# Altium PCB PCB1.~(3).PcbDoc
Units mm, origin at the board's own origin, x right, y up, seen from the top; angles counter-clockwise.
Board outline 100 x 50 mm, 2 copper layers (Top Layer, Bottom Layer); 61 components, 56 nets, 212 pads, 57 vias.
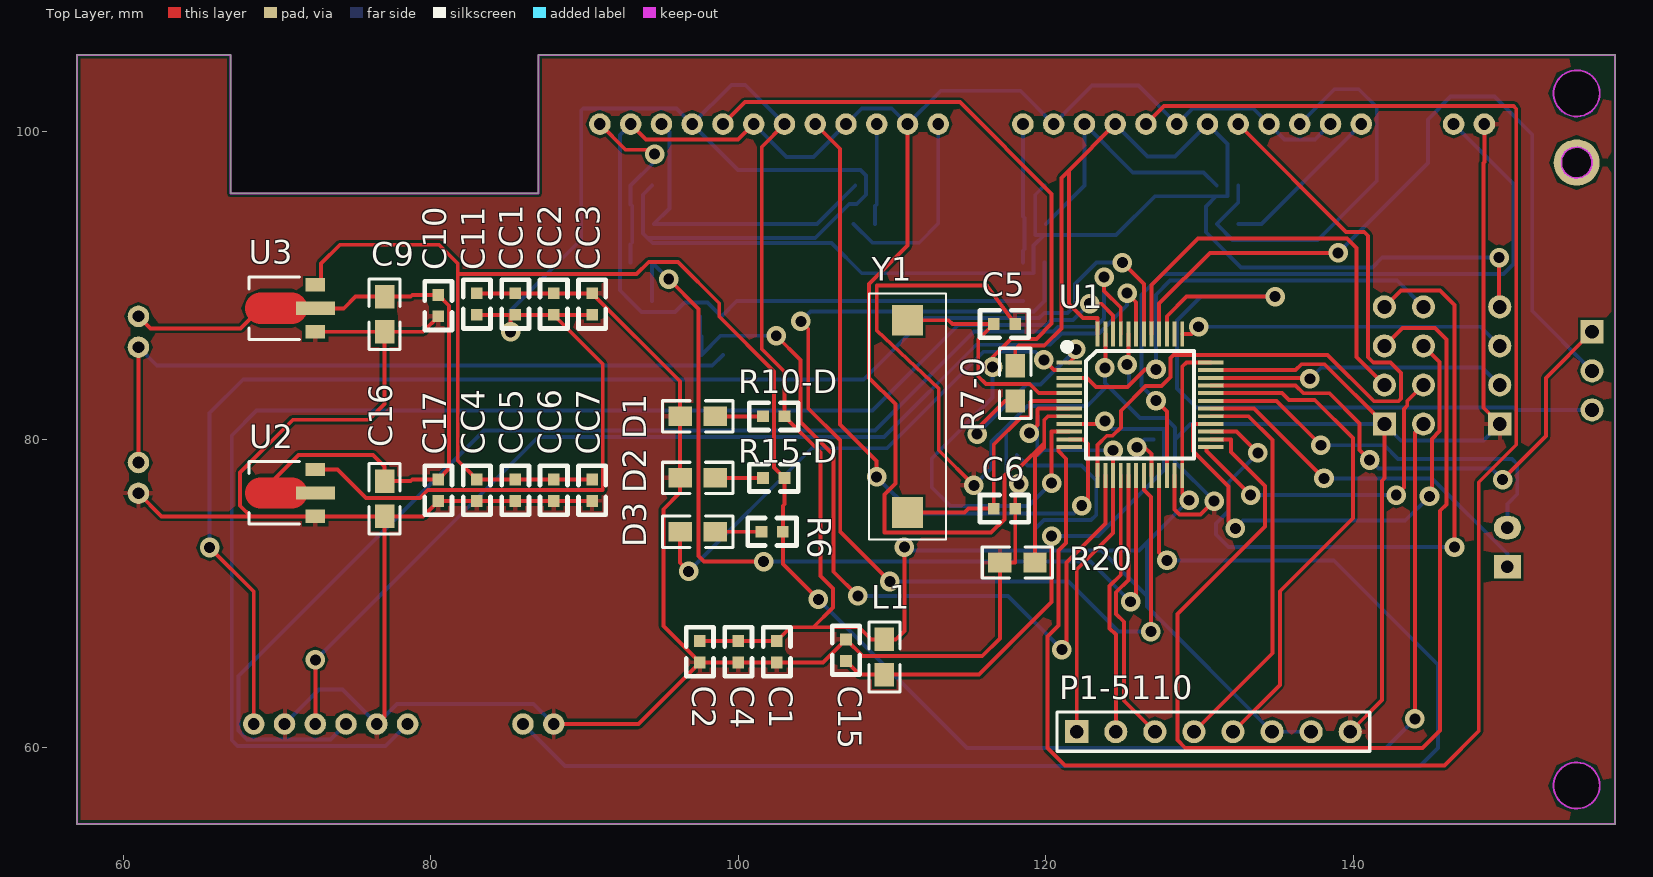
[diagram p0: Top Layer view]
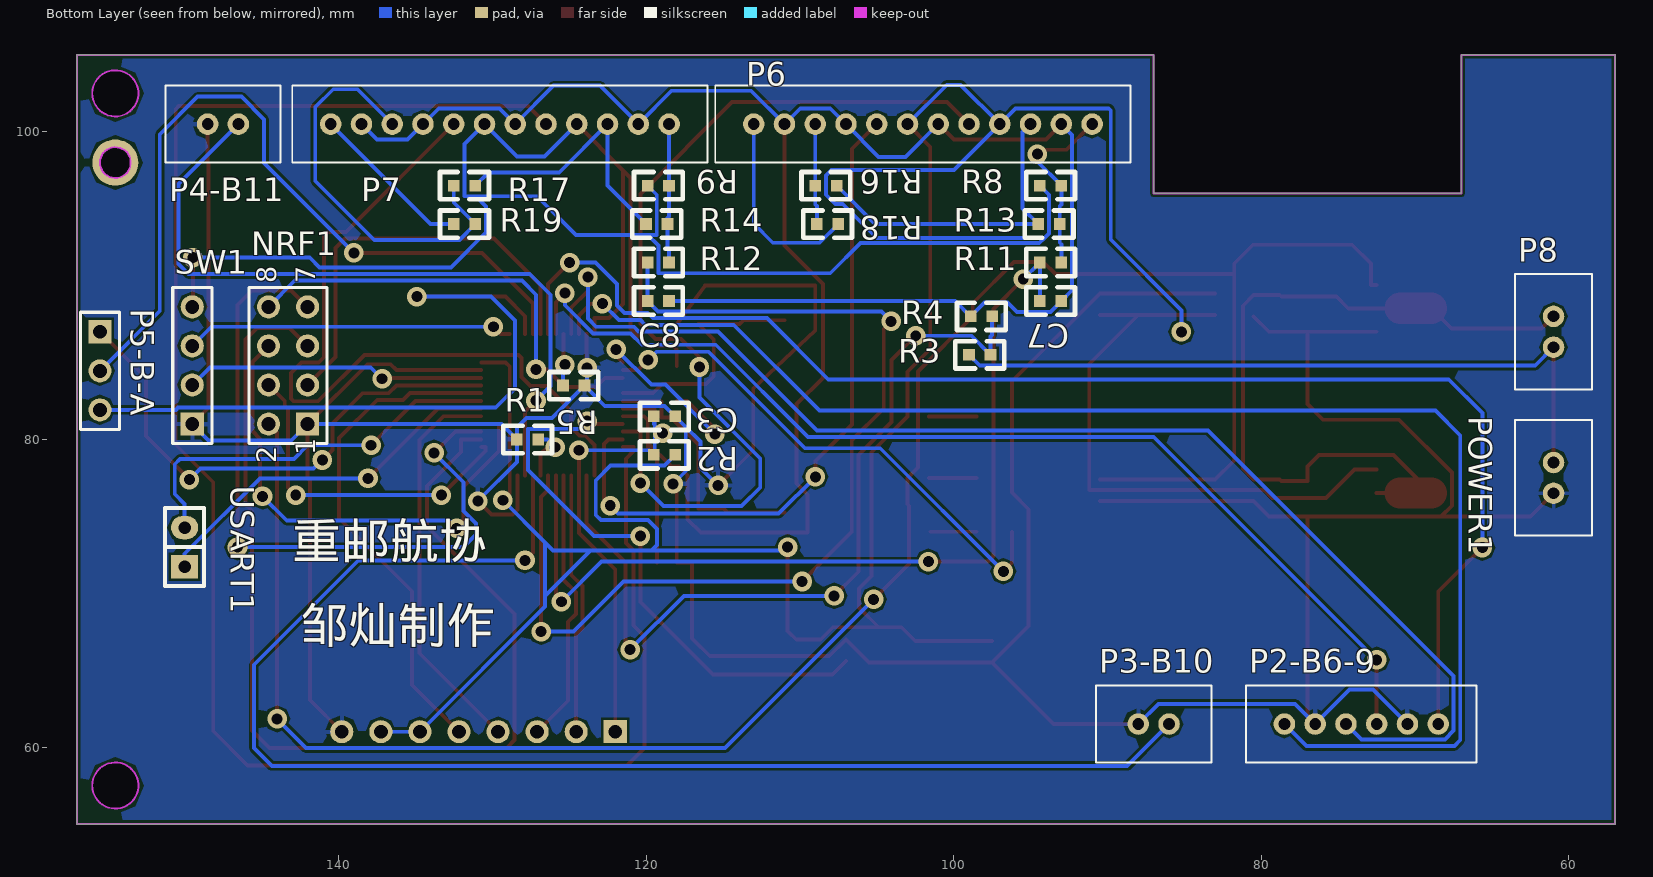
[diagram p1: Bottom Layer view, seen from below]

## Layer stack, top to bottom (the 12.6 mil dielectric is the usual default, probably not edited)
Top Solder: solder mask 0.0102, Solder Resist, Dk 3.5
Top Layer: signal copper 0.0356
Dielectric 1: dielectric 0.32, FR-4, Dk 4.8
Bottom Layer: signal copper 0.0356
Bottom Solder: solder mask 0.0102, Solder Resist, Dk 3.5

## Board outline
57,55 57,105 67,105 67,96 87,96 87,105 157,105 157,55

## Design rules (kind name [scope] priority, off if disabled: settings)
Clearance [All] p1: gap=0.178
PolygonConnect [All] p1: connectstyle=Relief reliefconductorwidth=0.254 reliefentries=4 polygonreliefangle="90 Angle" airgapwidth=0.254
RoutingVias [All] p1: holewidth=0.711 width=1.27 viastyle="Through Hole" minholewidth=0.711 minwidth=1.27 maxholewidth=0.711 maxwidth=1.27
SolderMaskExpansion [All] p1: expansion=0.102
UnpouredPolygon [All] p1: allowunpoured=FALSE
Width [All] p1: maxlimit=0.254 minlimit=0.254 preferedwidth=0.254
29 further rules are at their usual default settings.

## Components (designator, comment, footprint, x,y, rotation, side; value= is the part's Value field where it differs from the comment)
C1 "cap" 0603c 102.5,65.5 r90 top
C2 "cap" 0603c 97.5,65.5 r90 top
C3 "cap" 0603c 118.103,81.5 r0 bottom
C4 "cap" 0603c 100,65.5 r90 top
C5 "cap" 0603c 118,87.5 r180 top
C6 "cap" 0603c 118,75.5 r180 top
C7 "cap" 0603c 93,89 r0 bottom
C8 "cap" 0603c 118.5,89 r0 bottom
C9 "cap" 0805 77,87 r90 top
C10 "cap" 0603c 80.5,88 r90 top
C11 "cap" 0603c 83,89.5 r270 top
C15 "cap" 0603c 107,67 r270 top
C16 "cap" 0805 77,75 r90 top
C17 "cap" 0603c 80.5,76 r90 top
CC1 "cap" 0603c 85.5,89.5 r270 top
CC2 "cap" 0603c 88,89.5 r270 top
CC3 "cap" 0603c 90.5,89.5 r270 top
CC4 "cap" 0603c 83,76 r90 top
CC5 "cap" 0603c 85.5,76 r90 top
CC6 "cap" 0603c 88,76 r90 top
CC7 "cap" 0603c 90.5,76 r90 top
D1 "LED0" 0805 98.5,81.5 r180 top
D2 "LED0" 0805 98.5,77.5 r180 top
D3 "LED0" 0805 98.5,74 r180 top
L1 "Inductor" 0805 109.5,67 r270 top
NRF1 "Header 4X2" HDR2X4 142,81 r90 bottom
P1-5110 "Header 8" HDR1X8 122,61 r0 top
P2-B6-9 "Header 6" 6p 73.5,61.5 r0 bottom
P3-B10 "Header 2" 2p 87,61.5 r0 bottom
P4-B11 "Header 2" 2p 147.5,100.5 r0 bottom
P5-B-A "Header 3" HDR1X3 155.5,87 r270 bottom
P6 "Header 12" 12p 102,100.5 r0 bottom
P7 "Header 12" 12p 129.5,100.5 r0 bottom
P8 "Header 2" 2p 61,87 r90 bottom
POWER1 "CON2" 2p 61,77.5 r90 bottom
R1 "res" 0603c 127,80 r0 bottom
R2 "10K" 0603c 119.5,79 r180 bottom
R3 "10K" 0603c 97.603,85.5 r0 bottom
R4 "10K" 0603c 98.897,88 r180 bottom
R5 "res" 0603c 124,83.5 r0 bottom
R6 "1K" 0603c 101.5,74 r0 top
R7-0 "0R" 0805 118,82.5 r90 top
R8 "10K" 0603c 93,96.5 r0 bottom
R9 "10K" 0603c 118.5,96.5 r0 bottom
R10-D "res" 0603c 103,81.5 r180 top
R11 "1K" 0603c 93,91.5 r0 bottom
R12 "1K" 0603c 118.5,91.5 r0 bottom
R13 "10K" 0603c 94.5,94 r180 bottom
R14 "10K" 0603c 120,94 r180 bottom
R15-D "res" 0603c 103,77.5 r180 top
R16 "10K" 0603c 109,96.5 r180 bottom
R17 "10K" 0603c 132.5,96.5 r180 bottom
R18 "10K" 0603c 107.5,94 r0 bottom
R19 "10K" 0603c 132.5,94 r180 bottom
R20 "0R" 0805 117,72 r0 top
SW1 "Header 4" HDR1X4 149.5,81 r90 bottom
U1 "STM32F103C8T6" LQFP48S 121.5,85 r0 top
U2 "XC6203E" SOT-89 72.5,75 r90 top
U3 "XC6203E" SOT-89 72.5,87 r90 top
USART1 "CON2" SIP2 150,73 r90 bottom
Y1 "5032xtal" 晶振 111,81.5 r90 top

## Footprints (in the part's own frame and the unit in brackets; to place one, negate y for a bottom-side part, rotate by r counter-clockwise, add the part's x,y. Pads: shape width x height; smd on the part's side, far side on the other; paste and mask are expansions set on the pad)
2p [mil]
  round 55 hole 30: 1(-39.37,0) 2(39.37,0)
  silkscreen extent -148,-98 148,98
6p [mil]
  round 55 hole 30: 1(-196.85,0) 2(-118.11,0) 3(-39.37,0) 4(39.37,0) 5(118.11,0) 6(196.85,0)
  silkscreen extent -295,-98 295,98
12p [mil]
  round 55 hole 30: 1(-433.07,0) 2(-354.33,0) 3(-275.59,0) 4(-196.85,0) 5(-118.11,0) 6(-39.37,0) 7(39.37,0) 8(118.11,0) 9(196.85,0) 10(275.59,0) 11(354.33,0) 12(433.07,0)
  silkscreen extent -531,-98 531,98
0603c [mil]
  rect 30x30 smd: 1(0,0) 2(55,0)
  silkscreen extent -35,-35 90,35
0805 [mil]
  rect 60x50 smd: 1(0,0) 2(90,0)
  silkscreen extent -45,-40 135,40
HDR1X3 [mm] "Connector; Header; 3 Position"
  rect 1.5x1.5 hole 0.9: 1(0,0)
  round 1.5 hole 0.9: 2(2.54,0) 3(5.08,0)
  silkscreen extent -1.27,-1.27 6.35,1.27
HDR1X4 [mm] "Connector; Header; 4 Position"
  rect 1.5x1.5 hole 0.9: 1(0,0)
  round 1.5 hole 0.9: 2(2.54,0) 3(5.08,0) 4(7.62,0)
  silkscreen extent -1.27,-1.27 8.89,1.27
HDR1X8 [mm] "Connector; Header; 8 Position"
  rect 1.5x1.5 hole 0.9: 1(0,0)
  round 1.5 hole 0.9: 2(2.54,0) 3(5.08,0) 4(7.62,0) 5(10.16,0) 6(12.7,0) 7(15.24,0) 8(17.78,0)
  silkscreen extent -1.27,-1.27 19.05,1.27
HDR2X4 [mm] "Connector; Header; 4x2 Position"
  rect 1.5x1.5 hole 0.9: 1(0,0)
  round 1.5 hole 0.9: 2(0,2.54) 3(2.54,0) 4(2.54,2.54) 5(5.08,0) 6(5.08,2.54) 7(7.62,0) 8(7.62,2.54)
  silkscreen extent -1.27,-1.27 8.89,3.81
LQFP48S [mil] "DPIN-0.5"
  rect 65x10 smd: 1(0.43,0.29) 2(0.43,-19.39) 3(0.43,-39.08) 4(0.43,-58.76) 5(0.43,-78.45) 6(0.43,-98.13) 7(0.43,-117.82) 8(0.43,-137.5) 9(0.43,-157.19) 10(0.43,-176.87) 11(0.43,-196.56) 12(0.43,-216.24) 25(362.63,-216.24) 26(362.63,-196.56) 27(362.63,-176.87) 28(362.63,-157.19) 29(362.63,-137.5) 30(362.63,-117.82) 31(362.63,-98.13) 32(362.63,-78.45) 33(362.63,-58.76) 34(362.63,-39.08) 35(362.63,-19.39) 36(362.63,0.29)
  rect 10x65 smd: 13(73.26,-289.08) 14(92.95,-289.08) 15(112.63,-289.08) 16(132.32,-289.08) 17(152,-289.08) 18(171.69,-289.08) 19(191.37,-289.08) 20(211.06,-289.08) 21(230.74,-289.08) 22(250.43,-289.08) 23(270.11,-289.08) 24(289.8,-289.08) 37(289.8,73.13) 38(270.11,73.13) 39(250.43,73.13) 40(230.74,73.13) 41(211.06,73.13) 42(191.37,73.13) 43(171.69,73.13) 44(152,73.13) 45(132.32,73.13) 46(112.63,73.13) 47(92.95,73.13) 48(73.26,73.13)
  silkscreen extent -10,-246 319,46
SIP2 [mil]
  rect 60x70 hole 32: 1(-50,0)
  oval 60x70 hole 32: 2(50,0)
  silkscreen extent -100,-50 100,50
SOT-89 [mil]
  rect 34x50 smd: 1(0,0) 3(120,0)
  rect 34x100 smd: 2(60,0)
  Top Layer lines w80: 60,140 60,60
  silkscreen extent -20,40 140,170
晶振 [mm]
  rect 2x2 smd: 1(-6.25,0) 2(6.25,0)
  silkscreen extent -8,-2.5 8,2.5

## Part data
D1 D2 D3: "Typical INFRARED GaAs LED"
NRF1: "Header, 4-Pin, Dual row"
P1-5110: "Header, 8-Pin"
P2-B6-9: "Header, 6-Pin"
P3-B10 P4-B11 P8: "Header, 2-Pin"
P5-B-A: "Header, 3-Pin"
P6 P7: "Header, 12-Pin"
R2 R3 R4 R6 R7-0 R8 R9 R11 R12 R13 R14 R16 R17 R18 R19 R20: library part RES
SW1: "Header, 4-Pin"
U2 U3: library part XC6203

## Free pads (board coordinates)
  round 3 hole 3: 0(154.5,102.5) 1(154.5,57.5)
  round 3 hole 2: 2(154.5,98)

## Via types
v1: diameter 1.27, hole 0.711, Top Layer to Bottom Layer, 57 vias

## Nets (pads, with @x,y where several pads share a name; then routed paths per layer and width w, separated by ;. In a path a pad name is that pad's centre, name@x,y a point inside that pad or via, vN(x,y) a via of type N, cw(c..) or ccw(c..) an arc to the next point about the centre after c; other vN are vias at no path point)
3.3_2: CC4.2 CC5.2 CC6.2 CC7.2 NRF1.2 R6.2 R15-D.1 U3.3 | length 137.1
  Top Layer w0.254: U3.3 72.873,90.048 72.873,91.44 74.092,92.659 80.543,92.659 81.763,91.44 81.763,90.754 ; CC7.2 CC6.2 CC5.2 CC4.2 81.763,78.634 81.763,90.754 ; v1(105.207,69.596) 102.897,71.906 R6.2 102.897,75.692 103,75.795 R15-D.1 102.311,78.189 102.311,84.43 98.761,87.979 98.761,88.854 96.066,91.549 94.176,91.549 93.382,90.754 81.763,90.754 ; v1(143.986,61.828) 143.986,80.446 NRF1.2
  Bottom Layer w0.254: v1(105.207,69.596) 114.859,59.944 142.102,59.944 v1(143.986,61.828)
3.3V: C1.2 C2.2 C4.2 C11.2 CC1.2 CC2.2 CC3.2 L1.1 P1-5110.6 P1-5110.7 P6.4 P6.7 P7.4 P7.7 R2.2 R7-0.2 R8.2 R9.2 R10-D.1 SW1.4 U1.24 U1.36 U1.48 U2.3 | length 349
  Top Layer w0.254: U2.3 73.946,78.048 75.794,76.2 79.299,76.2 79.807,76.708 91.186,76.708 91.186,84.917 CC2.2 ; C11.2 CC1.2@85.192,88.103 ; v1(85.192,86.995) CC1.2@85.192,88.103 ; CC3.2 CC2.2 ; C2.2 C4.2 C1.2 103.396,67.793 104.869,67.793 ; P6.7 101.524,99.024 101.524,85.877 103,84.401 R10-D.1 105.331,79.169 105.331,71.12 106.147,70.305 106.147,69.07 104.869,67.793 ; v1(110.795,73) 110.795,67.559 110.236,67 L1.1 108.641,67 107.848,67.793 104.869,67.793 ; R7-0.2 118,85.852 118.254,86.106 119.888,86.106 121.006,87.224 121.006,97.006 121.488,97.488 ; U1.48 123.361,87.884 122.403,87.884 121.488,88.798 121.488,97.488 ; P7.4 121.488,97.488 ; v1(129.311,76.048) 128.861,76.498 U1.24 128.861,84.735 129.134,85.007 U1.36 ; v1(149.454,91.821) 149.454,88.666 SW1.4 ; CC1.2@85.192,88.103 CC1.2 CC2.2
  Bottom Layer w0.254: v1(85.192,86.995) 85.192,88.392 89.789,92.989 89.789,101.397 89.916,101.524 95.976,101.524 P6.4 ; R8.2 93.802,95.905 93.802,93.396 94.107,93.091 ; P6.7 100.452,103.048 99.548,103.048 P6.4 ; v1(110.795,73) 111.024,72.77 123.622,72.77 126.568,69.825 ; R2.2 118.795,78.308 122.301,78.308 123.266,77.343 123.266,75.082 122.936,74.752 119.863,74.752 119.278,74.168 119.278,73.127 119.634,72.771 126.035,72.771 126.568,73.304 ; R9.2 119.304,95.907 119.304,93.294 119.888,93.294 ; P7.4 126.6,98.4 128.4,98.4 P7.7 131.801,99.199 131.801,95.809 131.064,95.809 ; v1(129.311,76.048) 126.568,73.304 ; P1-5110.7 P1-5110.6 126.568,69.132 126.568,69.825 ; v1(149.454,91.821) 141.862,91.821 141.226,91.185 132.69,91.185 130.404,93.472 130.404,95.148 131.064,95.809 ; 94.107,93.091 94.437,92.761 106.07,92.761 108.026,90.805 119.202,90.805 119.202,92.608 119.888,93.294 ; 94.107,93.091 105.004,93.091 107.213,95.301 107.696,95.301 108.306,95.91 108.306,97.155 107.95,97.511 99.989,97.511 P6.4 ; 119.888,93.294 124.562,93.294 127.076,95.809 131.064,95.809 ; 126.568,69.825 126.568,73.304
ADC_KEY_L: C7.2 R11.2 U1.18 | length 60.5
  Top Layer w0.254: v1(95.479,90.418) 97.409,88.488 97.409,72.415 97.765,72.06 v1(101.651,72.06) ; v1(125.501,69.447) 125.861,69.807 U1.18
  Bottom Layer w0.254: C7.2 R11.2 v1(95.479,90.418) ; v1(101.651,72.06) 122.889,72.06 v1(125.501,69.447)
ADC_KEY_R: C8.2 R12.2 U1.19 | length 66.8
  Top Layer w0.254: v1(104.064,87.681) 104.546,87.198 104.546,82.017 106.629,79.934 106.629,73.99 v1(109.855,70.764) ; U1.19 126.361,76.708 126.822,76.247 v1(126.822,67.513)
  Bottom Layer w0.254: v1(104.064,87.681) 104.697,88.314 119.211,88.314 C8.2 R12.2 ; v1(109.855,70.764) 121.467,70.764 124.719,67.513 v1(126.822,67.513)
ADC_PITCH: P7.5 U1.12 | length 116.5
  Top Layer w0.254: U1.12 120.802,79.507 120.802,79.254 121.31,78.746 121.31,73.279 120.802,72.771 120.802,67.894 120.091,67.183 120.091,59.944 121.234,58.801 145.898,58.801 148.133,61.036 148.133,77.216 150.571,79.654 150.571,101.498 150.393,101.676 127.676,101.676 P7.5
ADC_POWER: R3.1 R4.2 U1.14 | length 54.2
  Top Layer w0.254: v1(102.464,86.741) 104.053,85.152 104.053,81.124 106.197,78.979 106.197,71.399 v1(107.772,69.825) ; v1(121.031,66.332) 121.323,66.624 121.323,72.011 123.861,74.549 U1.14
  Bottom Layer w0.254: R4.2 97.5,86.793 97.603,86.69 R3.1 98.844,86.741 v1(102.464,86.741) ; v1(107.772,69.825) 117.538,69.825 v1(121.031,66.332)
ADC_ROLL: P7.8 U1.13 | length 50.4
  Top Layer w0.254: U1.13 123.361,79.647 123.952,80.239 124.333,80.239 124.866,80.772 124.866,81.864 126.467,83.464 127.508,83.464 128.092,84.049 128.092,85.293 128.295,85.496 138.303,85.496 141.314,82.485 142.912,82.485 143.078,82.652 143.078,84.328 142.392,85.014 141.275,85.014 140.945,85.344 140.945,93.242 140.689,93.497 139.503,93.497 P7.8
ADC_THR: P6.5 U1.10 | length 61.1
  Top Layer w0.254: P6.5 100.43,101.93 114.402,101.93 120.371,95.961 120.371,87.525 119.383,86.538 117.729,86.538 116.535,85.344 v1(116.535,84.709) ; v1(120.371,77.165) 120.371,80.507 U1.10
  Bottom Layer w0.254: v1(116.535,84.709) 116.535,82.728 112.573,78.765 112.573,76.886 113.792,75.667 118.872,75.667 v1(120.371,77.165)
ADC_YAW: P6.8 U1.11 | length 44.6
  Top Layer w0.254: P6.8 106.603,98.897 106.603,80.976 108.991,78.588 v1(108.991,77.572) ; U1.11 122.428,80.007 122.733,79.703 122.733,76.1 v1(122.324,75.692)
  Bottom Layer w0.254: v1(108.991,77.572) 111.379,75.184 121.816,75.184 v1(122.324,75.692)
AGND: C7.1 C8.1 P6.2 P6.6 P6.9 P6.11 P7.2 P7.6 P7.9 P7.11 R4.1 R20.2 U1.8 | length 147.7
  Top Layer w0.254: P6.2 94.008,99.492 99.992,99.492 P6.6 ; P6.11 111,92.611 108.5,90.111 108.5,84.007 110.211,82.296 110.211,77.127 109.512,76.429 109.512,73.939 116.434,73.939 117.297,74.803 117.297,77.669 117.856,78.228 118.335,78.228 119.888,79.781 ; R20.2 119.286,78.875 119.888,79.477 119.888,79.781 ; U1.8 120.142,81.507 119.888,81.253 119.888,79.781
  Bottom Layer w0.254: P6.2 92.304,99.804 92.304,89.696 C7.1 93.71,88.29 95.885,88.29 96.495,88.9 97.997,88.9 R4.1 99.897,89 C8.1 ; P6.6 103.126,98.374 104.874,98.374 P6.9 108.024,101.524 109.976,101.524 P6.11 113.167,102.667 118.333,102.667 P7.2 122.997,102.997 126.003,102.997 P7.6 129.524,101.524 133.476,101.524 P7.9 135.508,99.492 137.492,99.492 P7.11
AVDD: C15.2 L1.2 U1.9 | length 38.2
  Top Layer w0.254: C15.2 107.889,64.714 L1.2 115.641,64.714 120.371,69.444 v1(120.371,73.711) ; U1.9 123.639,81.007 v1(123.825,81.194)
  Bottom Layer w0.254: v1(120.371,73.711) 123.393,73.711 127.686,78.003 127.686,80.686 124.333,80.686 v1(123.825,81.194)
BAT: P8.1 POWER1.2 R3.2 | length 46.3
  Top Layer w0.254: POWER1.2 P8.1
  Bottom Layer w0.254: P8.1 62.194,84.806 98.306,84.806 R3.2
BOOT0: R5.2 U1.44 | length 3.4
  Top Layer w0.254: v1(125.273,84.861) 125.361,84.949 U1.44
  Bottom Layer w0.254: v1(125.273,84.861) 125.397,84.737 R5.2
BOOT1: R1.1 U1.20 | length 3.8
  Top Layer w0.254: v1(125.908,79.492) 126.416,79.492 126.861,79.047 U1.20
  Bottom Layer w0.254: v1(125.908,79.492) 126.416,80 R1.1
CE: P1-5110.2 U1.16 | length 17.1
  Top Layer w0.254: P1-5110.2 124.54,67.306 124.13,67.716 124.13,70.46 124.861,71.191 U1.16
CLK: P1-5110.5 U1.32 | length 32.8
  Top Layer w0.254: U1.32 135.352,83.007 135.791,82.569 137.471,82.569 139.954,80.086 139.954,74.879 135.204,70.129 135.204,64.044 P1-5110.5
DC: P1-5110.3 U1.17 | length 18
  Top Layer w0.254: U1.17 125.361,70.864 124.562,70.065 124.562,68.656 125.07,68.148 125.07,63.01 P1-5110.3
DGND: C1.1 C2.1 C3.1 C4.1 C5.1 C6.1 C9.1 C10.1 C11.1 C15.1 C16.1 C17.1 CC1.1 CC2.1 CC3.1 CC4.1 CC5.1 CC6.1 CC7.1 D1.2 D2.2 NRF1.1 P1-5110.8 P2-B6-9.2 P2-B6-9.5 P3-B10.2 P4-B11.2 POWER1.1 R1.2 R5.1 R20.1 SW1.1 U1.23 U1.35 U1.47 U2.1 U3.1 | length 309.6
  Top Layer w0.254: POWER1.1 62.5,75 68.307,75 ; U3.1 C9.1 ; P2-B6-9.5 77,62 C16.1 ; C10.1 79.5,87 C9.1 ; C11.1 CC1.1 CC2.1 CC3.1 96.214,83.786 D1.2 D2.2 96.214,76.554 95.123,75.463 95.123,67.877 C2.1 ; P3-B10.2 93.5,61.5 C2.1 ; CC7.1 CC6.1 CC5.1 CC4.1 C17.1 79.5,75 C16.1 ; v1(115.316,77.013) 113.03,79.299 113.03,83.312 109,87.067 109,90 116.162,90 C5.1 ; v1(118.237,77.114) 118,76.877 C6.1 118,72 R20.1 117,67.056 115.857,65.913 108.087,65.913 C15.1 105.5,65.5 C1.1 C4.1 C2.1 ; v1(123.825,84.658) 123.861,84.694 U1.47 ; U1.23 128.361,75.438 128.691,75.108 130.048,75.108 v1(130.937,75.997) ; U1.35 136.222,84.507 136.602,84.887 138.113,84.887 NRF1.1 142,77.484 141.834,77.318 141.834,63.054 P1-5110.8 ; P4-B11.2 148.5,98.03 148.438,97.968 148.438,82.062 SW1.1 ; 68.307,75 U2.1 C16.1 ; 68.307,75 67.615,75.692 67.615,77.851 71.044,81.28 75.984,81.28 77,82.296 C9.1
  Bottom Layer w0.254: P2-B6-9.2 72.737,63.737 74.263,63.737 P2-B6-9.5 77.814,62.814 86.686,62.814 P3-B10.2 ; v1(115.316,77.013) 116.459,78.156 116.459,79.856 117.417,80.814 ; v1(118.237,77.114) 117.417,77.934 117.417,80.814 ; v1(123.825,84.658) 123.825,83.675 R5.1 ; v1(130.937,75.997) 128.397,78.537 R1.2 ; SW1.1 148.434,79.934 143.066,79.934 NRF1.1 129.397,81 R1.2 ; 117.417,80.814 C3.1 118.789,82.186 122.686,82.186 R5.1 ; R5.1 126.102,81.398 127.762,81.398 128.397,80.763 R1.2
DIN: P1-5110.4 U1.29 | length 25.7
  Top Layer w0.254: P1-5110.4 134.722,66.102 134.722,79.953 133.167,81.507 U1.29
KEY_1: P6.1 R8.1 R11.1 R13.2 | length 12.2
  Top Layer w0.254: P6.1 92.669,98.831 94.285,98.831 v1(94.564,98.552)
  Bottom Layer w0.254: R11.1 93,92.685 93.103,92.788 R13.2 93.103,95.174 93,95.277 R8.1 94.564,98.064 v1(94.564,98.552)
KEY_2: P6.3 R13.1 R16.2 | length 21.3
  Bottom Layer w0.254: P6.3 95.515,99.985 95.515,95.015 R13.1 105.103,94 R16.2
KEY_3: P6.10 R16.1 R18.2 | length 6.5
  Bottom Layer w0.254: R18.2 108.897,95.174 109,95.277 R16.1 P6.10
KEY_4: P6.12 R18.1 | length 13
  Bottom Layer w0.254: R18.1 108.714,92.786 111.76,92.786 113,94.026 P6.12
KEY_5: P7.1 R9.1 R12.1 R14.2 | length 9.1
  Bottom Layer w0.254: R12.1 118.5,92.261 118.603,92.364 R14.2 118.603,94.39 118.5,94.493 R9.1 P7.1
KEY_6: P7.3 R14.1 R17.2 | length 17.8
  Bottom Layer w0.254: R14.1 122.5,96.5 P7.3 125.642,97.358 130.245,97.358 R17.2
KEY_7: P7.10 R17.1 R19.2 | length 26.7
  Bottom Layer w0.254: R17.1 132.5,95.397 R19.2 132.139,92.964 137.668,92.964 141.503,96.799 141.503,101.6 140.335,102.768 138.768,102.768 P7.10
KEY_8: P7.12 R19.1 | length 10.7
  Bottom Layer w0.254: R19.1 134,94 P7.12
KEYY: U1.38
LED0: D3.2 U1.2 | length 34
  Top Layer w0.254: D3.2 96.214,71.985 v1(96.774,71.425) ; v1(119.863,85.166) 120.521,84.507 U1.2
  Bottom Layer w0.254: v1(96.774,71.425) 104.775,79.426 109.677,79.426 115.951,85.7 119.329,85.7 v1(119.863,85.166)
MISO: NRF1.7 U1.27 | length 47
  Top Layer w0.254: U1.27 132.395,80.507 v1(133.782,79.121) ; NRF1.7 143.067,89.687 145.618,89.687 146.558,88.748 v1(146.558,73)
  Bottom Layer w0.254: v1(133.782,79.121) 131.877,77.216 131.877,75.336 131.064,74.524 131.064,73.812 131.877,73 v1(146.558,73)
MOSI: NRF1.6 U1.28 | length 33
  Top Layer w0.254: U1.28 129.565,81.007 129.565,79.248 131.877,76.937 131.877,74.651 v1(132.309,74.219) ; NRF1.6 145.595,85.025 145.595,80.545 145.085,80.035 145.085,76.454 v1(144.932,76.302)
  Bottom Layer w0.254: v1(132.309,74.219) 132.817,74.727 143.358,74.727 v1(144.932,76.302)
NetC5_2: C5.2 U1.5 Y1.2 | length 15.9
  Top Layer w0.254: Y1.2 113.665,87.75 113.915,87.5 C5.2 115.595,86.492 115.595,84.099 116.103,83.591 118.948,83.591 119.532,83.007 U1.5
NetC6_2: C6.2 U1.6 Y1.1 | length 16.5
  Top Layer w0.254: Y1.1 114.706,75.25 114.956,75.5 C6.2 116.603,79.671 118.364,81.432 119.003,81.432 119.003,82.435 119.075,82.507 U1.6
NetD1_1: D1.1 R10-D.2 | length 3.1
  Top Layer w0.254: D1.1 R10-D.2
NetD2_1: D2.1 R15-D.2 | length 3.1
  Top Layer w0.254: D2.1 R15-D.2
NetD3_1: D3.1 R6.1 | length 3
  Top Layer w0.254: D3.1 R6.1
NetR7-0_1: R7-0.1 U1.1 | length 13.3
  Top Layer w0.254: v1(115.519,80.34) 115.519,80.67 117.349,82.5 R7-0.1 ; U1.1 121.945,85.442 v1(121.945,85.852)
  Bottom Layer w0.254: v1(115.519,80.34) 118.743,83.564 119.658,83.564 v1(121.945,85.852)
PA12: P5-B-A.1 U1.33 | length 34.5
  Top Layer w0.254: U1.33 136.222,83.507 136.729,83.001 138.422,83.001 140.386,81.037 140.386,79.324 v1(141.046,78.664) ; v1(149.682,77.394) 152.502,80.213 152.502,84.002 P5-B-A.1
  Bottom Layer w0.254: v1(141.046,78.664) 141.605,78.105 148.971,78.105 v1(149.682,77.394)
PB3: P5-B-A.3 U1.39 | length 47.7
  Top Layer w0.254: U1.39 127.861,88.011 129.131,89.281 v1(134.899,89.281)
  Bottom Layer w0.254: v1(134.899,89.281) 130.073,89.281 128.524,87.732 128.524,83.312 129.769,82.067 150.419,82.067 150.566,81.92 P5-B-A.3
PB4: P5-B-A.2 U1.40 | length 51.5
  Top Layer w0.254: U1.40 127.361,88.829 130.658,92.126 v1(138.989,92.126)
  Bottom Layer w0.254: v1(138.989,92.126) 144.831,97.968 144.831,100.813 146.304,102.286 149.149,102.286 151.613,99.822 151.613,88.347 P5-B-A.2
PB6: P2-B6-9.1 U1.42 | length 90.8
  Top Layer w0.254: v1(65.634,72.974) 68.5,70.108 P2-B6-9.1 ; v1(124.968,91.491) 126.361,90.098 U1.42
  Bottom Layer w0.254: v1(65.634,72.974) 65.634,81.712 67.818,83.896 108.153,83.896 112.139,87.882 119.558,87.882 119.888,88.212 121.41,88.212 121.895,88.697 121.895,90.106 123.279,91.491 v1(124.968,91.491)
PB7: P2-B6-9.3 U1.43 | length 70.2
  Top Layer w0.254: P2-B6-9.3 v1(72.5,65.667) ; v1(125.273,89.51) 125.861,88.922 U1.43
  Bottom Layer w0.254: v1(72.5,65.667) 86.995,80.162 109.474,80.162 115.468,86.157 120.269,86.157 121.006,86.893 123.444,86.893 125.273,88.722 v1(125.273,89.51)
PB8: P2-B6-9.4 U1.45 | length 83.9
  Top Layer w0.254: v1(123.774,90.551) 123.774,89.654 124.861,88.568 U1.45
  Bottom Layer w0.254: P2-B6-9.4 73.497,60.497 68.072,60.497 67.497,61.072 67.497,64.626 83.464,80.594 108.891,80.594 115.316,87.019 120.481,87.019 120.788,87.325 123.241,87.325 123.774,87.859 v1(123.774,90.551)
PB9: P2-B6-9.6 U1.46 | length 94.4
  Top Layer w0.254: v1(122.834,88.824) 123.602,88.824 124.361,88.065 U1.46
  Bottom Layer w0.254: P2-B6-9.6 77.065,60.065 67.452,60.065 67.065,60.452 67.065,80.264 68.674,81.873 108.722,81.873 114.3,87.451 120.049,87.451 120.356,87.757 121.768,87.757 v1(122.834,88.824)
PB10: P3-B10.1 U1.21 | length 92.7
  Top Layer w0.254: U1.21 127.361,72.644 v1(127.869,72.136)
  Bottom Layer w0.254: P3-B10.1 88.724,58.776 144.323,58.776 145.491,59.944 145.491,65.354 138.709,72.136 v1(127.869,72.136)
PB11: P4-B11.1 U1.22 | length 48.1
  Top Layer w0.254: v1(127.152,82.525) 127.861,81.816 U1.22
  Bottom Layer w0.254: v1(127.152,82.525) 126.213,83.464 126.213,89.408 127.558,90.753 149.732,90.753 150.393,91.415 150.393,96.607 P4-B11.1
RST: C3.2 P1-5110.1 R2.1 U1.7 U1.15 | length 32
  Top Layer w0.254: v1(118.923,80.416) 119.456,80.95 119.456,81.94 119.523,82.007 U1.7 ; P1-5110.1 122,71.553 124.361,73.914 U1.15 v1(124.361,79.299)
  Bottom Layer w0.254: v1(118.923,80.416) 119.431,80.924 ; v1(124.361,79.299) 119.799,79.299 R2.1 119.431,79.069 119.431,80.924 ; 119.431,80.924 119.5,80.994 C3.2 119.431,81.431 119.431,80.924
SWCLK: SW1.3 U1.37 | length 21.3
  Top Layer w0.254: U1.37 129.453,86.857 v1(129.921,87.325)
  Bottom Layer w0.254: v1(129.921,87.325) 148.255,87.325 SW1.3
SWDIO: SW1.2 U1.34 | length 19.6
  Top Layer w0.254: U1.34 137.1,84.007 v1(137.16,83.947)
  Bottom Layer w0.254: v1(137.16,83.947) 137.897,84.684 148.356,84.684 SW1.2
USART1_RX: U1.31 USART1.2 | length 26
  Top Layer w0.254: U1.31 134.988,82.507 v1(137.872,79.624)
  Bottom Layer w0.254: v1(137.872,79.624) 142,79.624 142.884,78.74 150.287,78.74 150.64,78.386 150.64,76.447 150,75.807 USART1.2
USART1_TX: U1.30 USART1.1 | length 24
  Top Layer w0.254: U1.30 133.537,82.007 v1(138.074,77.47)
  Bottom Layer w0.254: v1(138.074,77.47) 145.098,77.47 150,72.568 USART1.1
VCC: C9.2 C10.2 C16.2 C17.2 P8.2 U2.2 U3.2 | length 46.7
  Top Layer w0.254: P8.2 61.776,87.224 67.644,87.224 68.944,88.524 ; 68.944,76.524 71.414,78.994 76.238,78.994 77,78.232 C16.2 78.689,77.286 78.8,77.397 C17.2 81.204,78.101 81.204,88.693 C10.2 78.8,89.397 78.689,89.286 C9.2 75.108,89.286 74.346,88.524 U3.2 70.976,88.524 ; 70.976,76.524 U2.2
W_CE: NRF1.3 U1.41 | length 27.7
  Top Layer w0.254: U1.41 126.861,90.043 129.883,93.066 139.573,93.066 140.183,92.456 140.183,85.357 NRF1.3
W_CSN: NRF1.4 U1.25 | length 22
  Top Layer w0.254: U1.25 130.429,79.507 130.429,79.248 v1(133.299,76.378) ; v1(142.773,76.378) 143.281,76.886 143.281,81.99 143.487,82.195 143.487,82.487 NRF1.4
  Bottom Layer w0.254: v1(133.299,76.378) v1(142.773,76.378)
W_IRQ: NRF1.8 U1.3 | length 29.7
  Top Layer w0.254: U1.3 122.657,84.007 123.25,83.414 125.298,83.414 126.441,84.557 v1(127.152,84.557)
  Bottom Layer w0.254: v1(127.152,84.557) 127.152,89.408 128.066,90.322 142.838,90.322 NRF1.8
W_SCK: NRF1.5 U1.26 | length 72.3
  Top Layer w0.254: U1.26 132.029,80.007 132.029,79.172 134.239,76.962 134.239,74.346 128.549,68.656 128.549,60.452 129.057,59.944 144.475,59.944 145.618,61.087 145.618,75.362 146.027,75.77 146.027,86.51 145.288,87.249 143.169,87.249 NRF1.5
pads on no net: U1.4

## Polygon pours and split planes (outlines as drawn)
DGND on Top Paste "Top Layer-No Net" (solid, remove dead copper, shelved): 52,112.5 50,110.5 50,45.5 167,45.5 170.5,49 161,58.5 161,109.5
DGND on Top Layer "Top Layer-No Net" (solid, remove dead copper, pour order 3): 49.5,111.5 49.5,52 54.5,47 55.5,48 167,48 167,100.5 157.5,110
DGND on Bottom Layer "Top Layer-No Net" (solid, remove dead copper, pour order 5): 45,113 51.5,106.5 51.5,46.5 163,46.5 164.5,48 158,54.5 158,110.5

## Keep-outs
Keep-Out Layer:
  circle w0.127: c154.5,98 r1
  circle w0.127: c154.5,57.5 r1.5
  circle w0.127: c154.5,102.5 r1.5
  lines w0.127: 57,55 157,55 157,105 87,105 87,96 67,96 67,105 57,105 57,55

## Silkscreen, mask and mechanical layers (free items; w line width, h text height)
Bottom Overlay:
  text "重邮航协" at 143,71.5 h4
  text "邹灿制作" at 142.5,66 h4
